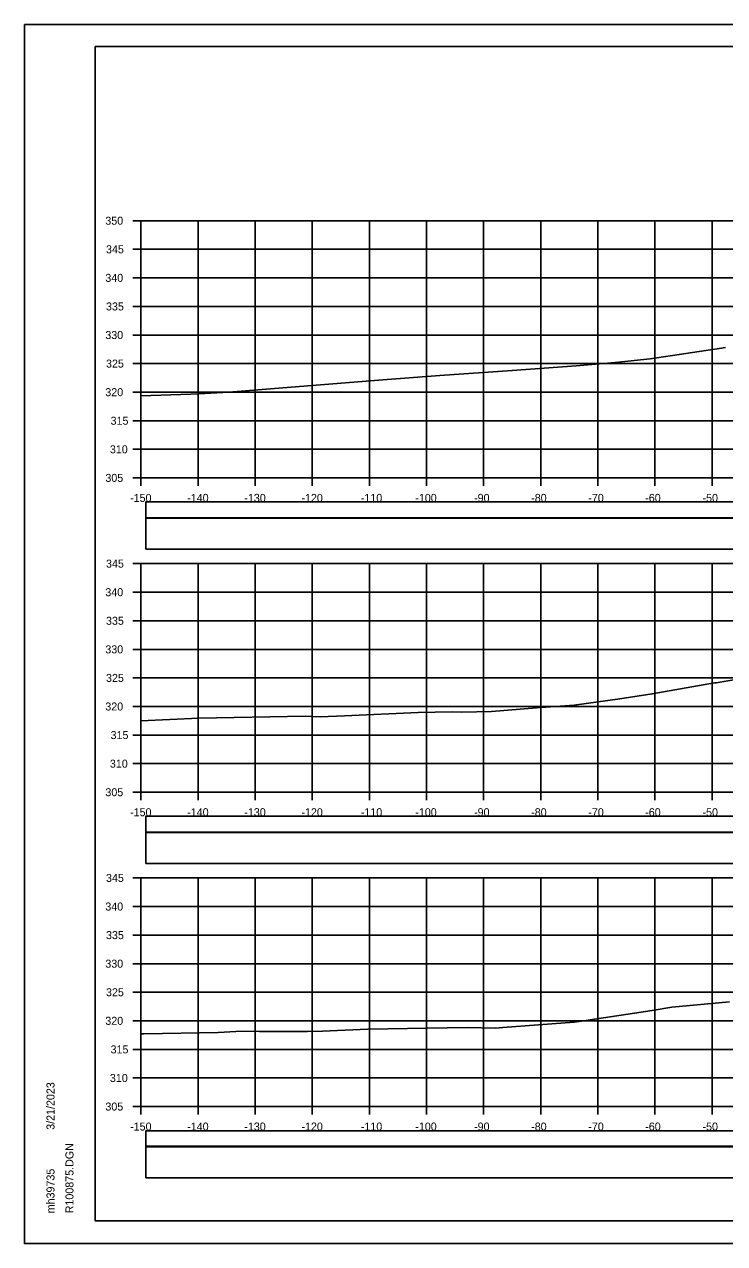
# Model space of a CAD drawing. Extents: x 1368122 to 1710785, y 373130 to 557566.
# Drawn here: x 1369185.2 to 1369307.8, y 373130.3 to 373343.7 of the extents above; entities that cross this region are included whole.
import ezdxf

# ---------------------------------------------------------------- set-up
doc = ezdxf.new("R2010")
doc.units = 0
for name, color, linetype in [('R_Axis', 7, 'Continuous'), ('R_Axis Annot', 7, 'Continuous'), ('R_Border', 7, 'Continuous'), ('R_Exist Surface', 7, 'Continuous'), ('R_Grid', 7, 'Continuous'), ('R_No Plot', 7, 'Continuous')]:
    doc.layers.add(name, color=color, linetype=linetype)

msp = doc.modelspace()

# ---------------------------------------------------------------- linework, layer by layer
for points in [[(1369206.41, 373257.3), (1369504.71, 373257.3), (1369504.71, 373260.12), (1369206.41, 373260.12)], [(1369206.41, 373251.83), (1369504.71, 373251.83), (1369504.71, 373257.25), (1369206.41, 373257.25)], [(1369206.41, 373202.3), (1369504.71, 373202.3), (1369504.71, 373205.12), (1369206.41, 373205.12)], [(1369206.41, 373196.83), (1369504.71, 373196.83), (1369504.71, 373202.25), (1369206.41, 373202.25)], [(1369206.41, 373147.36), (1369504.71, 373147.36), (1369504.71, 373150.06), (1369206.41, 373150.06)], [(1369206.41, 373141.83), (1369511.7, 373141.83), (1369511.7, 373147.25), (1369206.41, 373147.25)]]:
    msp.add_lwpolyline(points, close=True)
at = {"layer": 'R_Axis'}
for p, q in [((1369204.16, 373309.31), (1369205.56, 373309.31)), ((1369205.56, 373264.31), (1369205.56, 373309.31)), ((1369204.16, 373304.31), (1369205.56, 373304.31)), ((1369204.16, 373299.31), (1369205.56, 373299.31)), ((1369204.16, 373294.31), (1369205.56, 373294.31)), ((1369204.16, 373289.31), (1369205.56, 373289.31)), ((1369204.16, 373284.31), (1369205.56, 373284.31)), ((1369204.16, 373279.31), (1369205.56, 373279.31)), ((1369204.16, 373274.31), (1369205.56, 373274.31)), ((1369204.16, 373269.31), (1369205.56, 373269.31)), ((1369204.16, 373264.31), (1369205.56, 373264.31)), ((1369205.56, 373264.31), (1369505.56, 373264.31)), ((1369205.56, 373262.91), (1369205.56, 373264.31)), ((1369215.56, 373262.91), (1369215.56, 373264.31)), ((1369225.56, 373262.91), (1369225.56, 373264.31)), ((1369235.56, 373262.91), (1369235.56, 373264.31)), ((1369245.56, 373262.91), (1369245.56, 373264.31)), ((1369255.56, 373262.91), (1369255.56, 373264.31)), ((1369265.56, 373262.91), (1369265.56, 373264.31)), ((1369275.56, 373262.91), (1369275.56, 373264.31)), ((1369285.56, 373262.91), (1369285.56, 373264.31)), ((1369295.56, 373262.91), (1369295.56, 373264.31)), ((1369305.56, 373262.91), (1369305.56, 373264.31)), ((1369204.16, 373249.31), (1369205.56, 373249.31)), ((1369205.56, 373209.31), (1369205.56, 373249.31)), ((1369204.16, 373244.31), (1369205.56, 373244.31)), ((1369204.16, 373239.31), (1369205.56, 373239.31)), ((1369204.16, 373234.31), (1369205.56, 373234.31)), ((1369204.16, 373229.31), (1369205.56, 373229.31)), ((1369204.16, 373224.31), (1369205.56, 373224.31)), ((1369204.16, 373219.31), (1369205.56, 373219.31)), ((1369204.16, 373214.31), (1369205.56, 373214.31)), ((1369204.16, 373209.31), (1369205.56, 373209.31)), ((1369205.56, 373209.31), (1369505.56, 373209.31)), ((1369205.56, 373207.91), (1369205.56, 373209.31)), ((1369215.56, 373207.91), (1369215.56, 373209.31)), ((1369225.56, 373207.91), (1369225.56, 373209.31)), ((1369235.56, 373207.91), (1369235.56, 373209.31)), ((1369245.56, 373207.91), (1369245.56, 373209.31)), ((1369255.56, 373207.91), (1369255.56, 373209.31)), ((1369265.56, 373207.91), (1369265.56, 373209.31)), ((1369275.56, 373207.91), (1369275.56, 373209.31)), ((1369285.56, 373207.91), (1369285.56, 373209.31)), ((1369295.56, 373207.91), (1369295.56, 373209.31)), ((1369305.56, 373207.91), (1369305.56, 373209.31)), ((1369204.16, 373194.31), (1369205.56, 373194.31)), ((1369205.56, 373154.31), (1369205.56, 373194.31)), ((1369204.16, 373189.31), (1369205.56, 373189.31)), ((1369204.16, 373184.31), (1369205.56, 373184.31)), ((1369204.16, 373179.31), (1369205.56, 373179.31)), ((1369204.16, 373174.31), (1369205.56, 373174.31)), ((1369204.16, 373169.31), (1369205.56, 373169.31)), ((1369204.16, 373164.31), (1369205.56, 373164.31)), ((1369204.16, 373159.31), (1369205.56, 373159.31)), ((1369204.16, 373154.31), (1369205.56, 373154.31)), ((1369205.56, 373154.31), (1369505.56, 373154.31)), ((1369205.56, 373152.91), (1369205.56, 373154.31)), ((1369215.56, 373152.91), (1369215.56, 373154.31)), ((1369225.56, 373152.91), (1369225.56, 373154.31)), ((1369235.56, 373152.91), (1369235.56, 373154.31)), ((1369245.56, 373152.91), (1369245.56, 373154.31)), ((1369255.56, 373152.91), (1369255.56, 373154.31)), ((1369265.56, 373152.91), (1369265.56, 373154.31)), ((1369275.56, 373152.91), (1369275.56, 373154.31)), ((1369285.56, 373152.91), (1369285.56, 373154.31)), ((1369295.56, 373152.91), (1369295.56, 373154.31)), ((1369305.56, 373152.91), (1369305.56, 373154.31))]:
    msp.add_line(p, q, dxfattribs=at)
at = {"layer": 'R_Border'}
for p, q in [((1369197.56, 373339.77), (1369513.74, 373339.77)), ((1369197.56, 373134.31), (1369197.56, 373339.77)), ((1369197.56, 373134.31), (1369197.56, 373134.31)), ((1369513.74, 373134.31), (1369197.56, 373134.31))]:
    msp.add_line(p, q, dxfattribs=at)
at = {"layer": 'R_Exist Surface'}
for points in [[(1369205.56, 373278.68), (1369214.32, 373278.98), (1369216.75, 373279.08), (1369220.94, 373279.31), (1369247.93, 373281.47), (1369257.93, 373282.24), (1369270.59, 373283.09), (1369281.77, 373283.9), (1369288.58, 373284.52), (1369294.73, 373285.15), (1369307.21, 373287.02), (1369307.54, 373287.07), (1369307.9, 373287.13)], [(1369205.56, 373221.8), (1369215.69, 373222.26), (1369234.33, 373222.61), (1369236.96, 373222.48), (1369241.21, 373222.65), (1369254.09, 373223.26), (1369260.04, 373223.36), (1369261.78, 373223.32), (1369266.94, 373223.44), (1369274.8, 373224.06), (1369281.44, 373224.57), (1369289.41, 373225.66), (1369295.1, 373226.5), (1369306.02, 373228.44), (1369306.26, 373228.46), (1369316.52, 373230.2)], [(1369205.56, 373167.05), (1369206.07, 373167.05), (1369219.11, 373167.28), (1369222.18, 373167.42), (1369225.61, 373167.49), (1369226.31, 373167.45), (1369234.75, 373167.42), (1369237.38, 373167.48), (1369245.29, 373167.86), (1369262.68, 373168.14), (1369267.67, 373168.03), (1369268.94, 373168.12), (1369281.45, 373169.08), (1369282.31, 373169.2), (1369295.07, 373171.09), (1369298.54, 373171.71), (1369308.62, 373172.65)]]:
    msp.add_lwpolyline(points, dxfattribs=at)
at = {"layer": 'R_Grid'}
for p, q in [((1369205.56, 373309.31), (1369505.56, 373309.31)), ((1369205.56, 373264.31), (1369205.56, 373309.31)), ((1369215.56, 373264.31), (1369215.56, 373309.31)), ((1369225.56, 373264.31), (1369225.56, 373309.31)), ((1369235.56, 373264.31), (1369235.56, 373309.31)), ((1369245.56, 373264.31), (1369245.56, 373309.31)), ((1369255.56, 373264.31), (1369255.56, 373309.31)), ((1369265.56, 373264.31), (1369265.56, 373309.31)), ((1369275.56, 373264.31), (1369275.56, 373309.31)), ((1369285.56, 373264.31), (1369285.56, 373309.31)), ((1369295.56, 373264.31), (1369295.56, 373309.31)), ((1369305.56, 373264.31), (1369305.56, 373309.31)), ((1369205.56, 373304.31), (1369505.56, 373304.31)), ((1369205.56, 373299.31), (1369505.56, 373299.31)), ((1369205.56, 373294.31), (1369505.56, 373294.31)), ((1369205.56, 373289.31), (1369505.56, 373289.31)), ((1369205.56, 373284.31), (1369505.56, 373284.31)), ((1369205.56, 373279.31), (1369505.56, 373279.31)), ((1369205.56, 373274.31), (1369505.56, 373274.31)), ((1369205.56, 373269.31), (1369505.56, 373269.31)), ((1369205.56, 373264.31), (1369505.56, 373264.31)), ((1369205.56, 373249.31), (1369505.56, 373249.31)), ((1369205.56, 373209.31), (1369205.56, 373249.31)), ((1369215.56, 373209.31), (1369215.56, 373249.31)), ((1369225.56, 373209.31), (1369225.56, 373249.31)), ((1369235.56, 373209.31), (1369235.56, 373249.31)), ((1369245.56, 373209.31), (1369245.56, 373249.31)), ((1369255.56, 373209.31), (1369255.56, 373249.31)), ((1369265.56, 373209.31), (1369265.56, 373249.31)), ((1369275.56, 373209.31), (1369275.56, 373249.31)), ((1369285.56, 373209.31), (1369285.56, 373249.31)), ((1369295.56, 373209.31), (1369295.56, 373249.31)), ((1369305.56, 373209.31), (1369305.56, 373249.31)), ((1369205.56, 373244.31), (1369505.56, 373244.31)), ((1369205.56, 373239.31), (1369505.56, 373239.31)), ((1369205.56, 373234.31), (1369505.56, 373234.31)), ((1369205.56, 373229.31), (1369505.56, 373229.31)), ((1369205.56, 373224.31), (1369505.56, 373224.31)), ((1369205.56, 373219.31), (1369505.56, 373219.31)), ((1369205.56, 373214.31), (1369505.56, 373214.31)), ((1369205.56, 373209.31), (1369505.56, 373209.31)), ((1369205.56, 373194.31), (1369505.56, 373194.31)), ((1369205.56, 373154.31), (1369205.56, 373194.31)), ((1369215.56, 373154.31), (1369215.56, 373194.31)), ((1369225.56, 373154.31), (1369225.56, 373194.31)), ((1369235.56, 373154.31), (1369235.56, 373194.31)), ((1369245.56, 373154.31), (1369245.56, 373194.31)), ((1369255.56, 373154.31), (1369255.56, 373194.31)), ((1369265.56, 373154.31), (1369265.56, 373194.31)), ((1369275.56, 373154.31), (1369275.56, 373194.31)), ((1369285.56, 373154.31), (1369285.56, 373194.31)), ((1369295.56, 373154.31), (1369295.56, 373194.31)), ((1369305.56, 373154.31), (1369305.56, 373194.31)), ((1369205.56, 373189.31), (1369505.56, 373189.31)), ((1369205.56, 373184.31), (1369505.56, 373184.31)), ((1369205.56, 373179.31), (1369505.56, 373179.31)), ((1369205.56, 373174.31), (1369505.56, 373174.31)), ((1369205.56, 373169.31), (1369505.56, 373169.31)), ((1369205.56, 373164.31), (1369505.56, 373164.31)), ((1369205.56, 373159.31), (1369505.56, 373159.31)), ((1369205.56, 373154.31), (1369505.56, 373154.31))]:
    msp.add_line(p, q, dxfattribs=at)
at = {"layer": 'R_No Plot'}
for p, q in [((1369185.16, 373343.66), (1369518.49, 373343.66)), ((1369185.16, 373130.33), (1369518.49, 373130.33))]:
    msp.add_line(p, q, dxfattribs=at)
for points in [[(1369185.15, 373343.66), (1369518.49, 373343.66), (1369518.49, 373130.33), (1369185.15, 373130.33)], [(1369431.48, 373339.77), (1369451.1, 373339.77), (1369451.1, 373329.89), (1369467.21, 373329.89), (1369490.41, 373329.89), (1369490.53, 373301.73), (1369513.74, 373301.73), (1369513.74, 373134.31), (1369197.56, 373134.31), (1369197.56, 373339.77)]]:
    msp.add_lwpolyline(points, close=True, dxfattribs=at)

# ---------------------------------------------------------------- texts
at = {"layer": 'R_Axis Annot'}
for s, p in [('350', (1369199.33, 373308.61)), ('345', (1369199.45, 373303.61)), ('340', (1369199.33, 373298.61)), ('335', (1369199.45, 373293.61)), ('330', (1369199.33, 373288.61)), ('325', (1369199.45, 373283.61)), ('320', (1369199.33, 373278.61)), ('315', (1369200.25, 373273.61)), ('310', (1369200.13, 373268.61)), ('305', (1369199.34, 373263.61)), ('-150', (1369203.67, 373260.11)), ('-140', (1369213.67, 373260.11)), ('-130', (1369223.67, 373260.11)), ('-120', (1369233.67, 373260.11)), ('-110', (1369244.07, 373260.11)), ('-100', (1369253.61, 373260.11)), ('-90', (1369263.9, 373260.11)), ('-80', (1369273.9, 373260.11)), ('-70', (1369283.9, 373260.11)), ('-60', (1369293.87, 373260.11)), ('-50', (1369303.9, 373260.11)), ('345', (1369199.45, 373248.61)), ('340', (1369199.33, 373243.61)), ('335', (1369199.45, 373238.61)), ('330', (1369199.33, 373233.61)), ('325', (1369199.45, 373228.61)), ('320', (1369199.33, 373223.61)), ('315', (1369200.25, 373218.61)), ('310', (1369200.13, 373213.61)), ('305', (1369199.34, 373208.61)), ('-150', (1369203.67, 373205.11)), ('-140', (1369213.67, 373205.11)), ('-130', (1369223.67, 373205.11)), ('-120', (1369233.67, 373205.11)), ('-110', (1369244.07, 373205.11)), ('-100', (1369253.61, 373205.11)), ('-90', (1369263.9, 373205.11)), ('-80', (1369273.9, 373205.11)), ('-70', (1369283.9, 373205.11)), ('-60', (1369293.87, 373205.11)), ('-50', (1369303.9, 373205.11)), ('345', (1369199.45, 373193.61)), ('340', (1369199.33, 373188.61)), ('335', (1369199.45, 373183.61)), ('330', (1369199.33, 373178.61)), ('325', (1369199.45, 373173.61)), ('320', (1369199.33, 373168.61)), ('315', (1369200.25, 373163.61)), ('310', (1369200.13, 373158.61)), ('305', (1369199.34, 373153.61)), ('-150', (1369203.67, 373150.11)), ('-140', (1369213.67, 373150.11)), ('-130', (1369223.67, 373150.11)), ('-120', (1369233.67, 373150.11)), ('-110', (1369244.07, 373150.11)), ('-100', (1369253.61, 373150.11)), ('-90', (1369263.9, 373150.11)), ('-80', (1369273.9, 373150.11)), ('-70', (1369283.9, 373150.11)), ('-60', (1369293.87, 373150.11)), ('-50', (1369303.9, 373150.11))]:
    msp.add_text(s, height=1.4, dxfattribs=at).set_placement(p)
at = {"layer": 'R_Border'}
for s, p in [('3/21/2023', (1369190.43, 373150.24)), ('R100875.DGN', (1369193.75, 373135.63)), ('mh39735', (1369190.43, 373135.63))]:
    msp.add_text(s, height=1.4, rotation=90, dxfattribs=at).set_placement(p)

doc.saveas('drawing.dxf')
